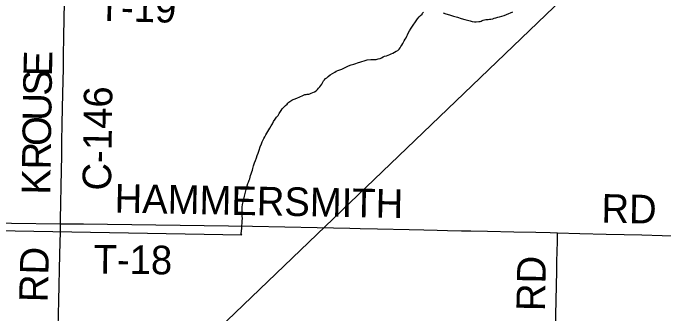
# Model space of a CAD drawing. Extents: x -483 to 680, y 0 to 440.
# Drawn here: x 121.8 to 186.6, y 218.9 to 248.8 of the extents above; entities that cross this region are included whole.
import ezdxf

# ---------------------------------------------------------------- set-up
doc = ezdxf.new("R2010")
doc.units = 0
for name, color, linetype in [('GM_X_County_Road', 7, 'Continuous'), ('GM_X_County_Road_Text', 7, 'Continuous'), ('GM_X_Minor_River', 7, 'Continuous'), ('GM_X_Township_Road', 7, 'Continuous'), ('GM_X_Township_Road_Text', 7, 'Continuous')]:
    doc.layers.add(name, color=color, linetype=linetype)

msp = doc.modelspace()

# ---------------------------------------------------------------- linework, layer by layer
at = {"layer": 'GM_X_County_Road'}
for points in [[(126.559, 227.882), (126.563, 228.311), (126.663, 233.22), (126.683, 234.619), (126.701, 235.985), (126.731, 237.85), (126.777, 240.833), (126.836, 243.317), (126.864, 244.529), (126.889, 246.518), (126.941, 249.874), (126.983, 252.888), (126.984, 252.996)], [(76.405, 228.209), (77.732, 228.207), (79.536, 228.205), (81.122, 228.199), (83.017, 228.168), (84.29, 228.169), (85.658, 228.165), (90.256, 228.152), (92.929, 228.14), (100.852, 228.125), (108.125, 228.103), (111.636, 228.062), (116.763, 227.999), (126.559, 227.882)]]:
    msp.add_lwpolyline(points, dxfattribs=at)
at = {"layer": 'GM_X_Minor_River'}
for points in [[(74.642, 128.314), (75.587, 153.634), (193.508, 266.565)], [(154.929, 243.447), (155.18, 243.572), (155.45, 243.658), (155.737, 243.724), (155.93, 243.794), (156.085, 243.865), (156.2, 243.899), (156.334, 243.933), (156.526, 243.984), (156.757, 244.052), (157.065, 244.156), (157.428, 244.201), (157.714, 244.192), (157.943, 244.203), (158.154, 244.253), (158.327, 244.304), (158.462, 244.357), (158.636, 244.446), (158.771, 244.518), (158.963, 244.569), (159.136, 244.62), (159.291, 244.691), (159.446, 244.762), (159.6, 244.833), (159.775, 244.922), (159.949, 245.03), (160.104, 245.101), (160.241, 245.23), (160.321, 245.341), (160.401, 245.472), (160.501, 245.621), (160.583, 245.789), (160.663, 245.92), (160.744, 246.05), (160.844, 246.218), (160.925, 246.349), (160.986, 246.499), (161.067, 246.648), (161.129, 246.798), (161.251, 247.042), (161.413, 247.322), (162.051, 248.233), (162.229, 248.436), (162.366, 248.565), (162.504, 248.693), (162.564, 248.786), (162.662, 248.878)], [(164.602, 248.814), (164.885, 248.728), (165.244, 248.621), (165.639, 248.494), (166.036, 248.386), (166.413, 248.259), (166.753, 248.172), (167.017, 248.087), (167.281, 248.021), (167.508, 247.976), (167.716, 247.931), (167.907, 247.943), (168.155, 247.954), (168.289, 247.969), (168.385, 248.004), (168.482, 248.058), (168.579, 248.111), (168.713, 248.145), (168.847, 248.16), (168.961, 248.156), (169.095, 248.17), (169.229, 248.185), (169.362, 248.199), (169.535, 248.232), (169.67, 248.284), (169.843, 248.336), (170.035, 248.386), (170.227, 248.437), (170.438, 248.487), (170.669, 248.575), (170.92, 248.662), (171.537, 248.927)], [(144.59, 226.784), (144.536, 226.881), (144.565, 227.185), (144.572, 227.413), (144.597, 227.602), (144.601, 227.735), (144.605, 227.868), (144.629, 228.019), (144.635, 228.191), (144.641, 228.4), (144.63, 228.628), (144.621, 228.952), (144.611, 229.238), (144.621, 229.542), (144.667, 229.806), (144.713, 230.052), (144.779, 230.335), (144.865, 230.618), (144.911, 230.883), (144.977, 231.166), (145.043, 231.43), (145.107, 231.656), (145.172, 231.882), (145.252, 232.032), (145.315, 232.201), (145.377, 232.351), (145.42, 232.502), (145.463, 232.671), (145.526, 232.84), (145.57, 233.029), (145.633, 233.217), (145.677, 233.387), (145.718, 233.5), (145.761, 233.651), (145.846, 233.933), (145.93, 234.178), (146.034, 234.441), (146.117, 234.666), (146.201, 234.911), (146.306, 235.192), (146.411, 235.512), (146.535, 235.813), (146.618, 236.019), (146.719, 236.206), (146.78, 236.337), (146.862, 236.524), (146.964, 236.73), (147.366, 237.383), (147.487, 237.607), (147.627, 237.812), (147.748, 238.036), (147.908, 238.259), (148.048, 238.463), (148.187, 238.649), (148.288, 238.836), (148.427, 239.022), (148.507, 239.133), (148.607, 239.282), (148.706, 239.412), (148.824, 239.522), (148.922, 239.614), (149.079, 239.761), (149.158, 239.853), (149.257, 239.964), (149.373, 240.017), (149.549, 240.164), (149.704, 240.235), (149.896, 240.304), (150.108, 240.373), (150.282, 240.444), (150.436, 240.515), (150.572, 240.586), (150.726, 240.657), (150.861, 240.71), (150.995, 240.724), (151.091, 240.74), (151.244, 240.754), (151.359, 240.788), (151.494, 240.841), (151.649, 240.912), (151.822, 240.982), (151.978, 241.091), (152.096, 241.201), (152.215, 241.35), (152.353, 241.497), (152.452, 241.627), (152.533, 241.757), (152.593, 241.87), (152.714, 242.075), (152.813, 242.186), (152.912, 242.296), (153.029, 242.388), (153.166, 242.516), (153.38, 242.661), (153.846, 242.95), (153.983, 243.041), (154.118, 243.094), (154.348, 243.162), (154.542, 243.251), (154.715, 243.321), (154.929, 243.447)], [(101.331, 227.543), (144.59, 226.784)]]:
    msp.add_lwpolyline(points, dxfattribs=at)
at = {"layer": 'GM_X_Township_Road'}
for points in [[(126.229, 214.414), (126.237, 214.912), (126.311, 217.584), (126.376, 220.226), (126.489, 224.857), (126.539, 227.095), (126.559, 227.882)], [(126.559, 227.882), (128.827, 227.871), (145.644, 227.633), (152.091, 227.506)], [(152.091, 227.506), (155.34, 227.442), (156.365, 227.422), (158.075, 227.378), (161.214, 227.316), (162.675, 227.287), (164.011, 227.261), (165.037, 227.232), (166.435, 227.199), (167.368, 227.175), (169.015, 227.137), (171.625, 227.084), (173.832, 227.042), (175.262, 227.005), (175.98, 226.987)], [(175.731, 201.981), (175.644, 202.34), (175.586, 202.71), (175.561, 203.039), (175.547, 203.386), (175.549, 203.914), (175.608, 206.215), (175.622, 207.458), (175.676, 211.501), (175.718, 213.304), (175.781, 217.347), (175.905, 223.224), (175.923, 224.125), (175.965, 226.115), (175.974, 226.644), (175.98, 226.987)], [(175.98, 226.987), (178.214, 226.929), (180.825, 226.865), (182.596, 226.826), (184.368, 226.777), (186.388, 226.736), (188.252, 226.689)]]:
    msp.add_lwpolyline(points, dxfattribs=at)

# ---------------------------------------------------------------- texts
at = {"layer": 'GM_X_County_Road_Text'}
for s, height, rotation, p in [('E', 2.841, 88.62199, (125.7, 242.5)), ('S', 2.841, 89.1233, (125.67, 240.591)), ('C-146', 2.8409, 89.18185, (131.576, 231.166)), ('U', 2.841, 89.13116, (125.633, 238.091)), ('O', 2.841, 89.13287, (125.595, 235.591)), ('R', 2.841, 89.13152, (125.559, 233.258)), ('K', 2.841, 89.13299, (125.522, 230.759))]:
    msp.add_text(s, height=height, rotation=rotation, dxfattribs=at).set_placement(p)
at = {"layer": 'GM_X_Township_Road_Text'}
for s, height, rotation, p in [('T-19', 2.8409, 358.58501, (130.227, 248.034)), ('HAMMERSMITH', 2.84091, 358.9155, (131.913, 228.998)), ('RD', 2.8409, 359.00866, (180.333, 227.997)), ('RD', 2.8409, 88.53832, (125.272, 220.069)), ('T-18', 2.8409, 359.29307, (129.83, 222.95)), ('RD', 2.8409, 89.01275, (174.732, 219.191))]:
    msp.add_text(s, height=height, rotation=rotation, dxfattribs=at).set_placement(p)

doc.saveas('drawing.dxf')
